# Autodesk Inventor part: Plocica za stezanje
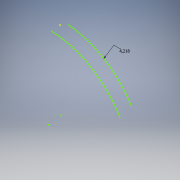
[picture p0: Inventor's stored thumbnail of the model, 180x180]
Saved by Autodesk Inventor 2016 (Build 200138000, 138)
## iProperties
Created: 2015-08
Part Number: Plocica za stezanje
Material: Generic
Document SubType Name: Modeling
Designer: Ugljesa
Density: 1 g/cm^3
Appearance: Default
Author: Ugljesa
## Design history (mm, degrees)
sketch "Sketch1"
  geometry: L1 (69.378, -24.389)-(80.09, -24.254); L2 (84.451, -26.699)-(90.64, -37.112); L3 (88.896, -43.965)-(71.593, -54.248); L4 (-11.189, -7.809)-(-11.443, 12.321); L5 (-6.506, 17.384)-(5.606, 17.537); L6 (9.967, 15.092)-(15.452, 5.864); L7 (-9.991, -102.669)-(-11.986, 55.36); C1 r 4.5 at (-1.375, 6.993) reference; C2 r 4.5 at (79.102, -38.153) reference; A1 r 90 centre (-9.991, -102.669) between (64.879, -52.725) and (-6.389, -12.742); A2 r 110 centre (-9.991, -102.669) between (65.866, -23.01) and (18.457, 3.588); A3 r 5 centre (5.669, 12.537) between (9.967, 15.092) and (5.606, 17.537); A4 r 5 centre (19.75, 8.418) between (15.452, 5.864) and (18.457, 3.588); A5 r 5 centre (69.315, -19.39) between (65.866, -23.01) and (69.378, -24.389); A6 r 5 centre (80.153, -29.254) between (84.451, -26.699) and (80.09, -24.254); A7 r 5 centre (86.342, -39.667) between (88.896, -43.965) and (90.64, -37.112); A8 r 5 centre (69.038, -49.95) between (64.879, -52.725) and (71.593, -54.248); A9 r 5 centre (-6.189, -7.746) between (-11.189, -7.809) and (-6.389, -12.742); A10 r 5 centre (-6.443, 12.384) between (-6.506, 17.384) and (-11.443, 12.321); 9 further points
  constraints: 26 point on circle, 16 tangent, 14 end point, 12 point on line, 10 centre point, 7 equal radius, 2 perpendicular, 1 coincident, 1 collinear
  dimensions: "d1" = 110 radius of A2; "d2" = 90 radius of A1; "d4" = 60 deg angle of L4 L3; "d5" = 30 distance of point (93.194, -41.41) point (67.405, -56.737); "d8" = 30 distance of point (-11.127, -12.677) point (-11.506, 17.321); "d9" = 10 distance from line of L4 C1.centre; "d10" = 10 distance from line of L3 C2.centre; "d11" = 20 distance of point (82.977, -24.218) point (93.194, -41.41); "d12" = 20 distance of point (-11.506, 17.321) point (8.493, 17.573); "d13" = 30 deg angle of L3 L1; "d14" = 30 deg angle of L7 L6; "d15" = 5 radius of A3
extrude "Extrusion1" new body sketch "Sketch1" distance "d16" = 5; taper "d17" = 0 deg
body "Solid1"
node "Reference1"
node "Reference2"
